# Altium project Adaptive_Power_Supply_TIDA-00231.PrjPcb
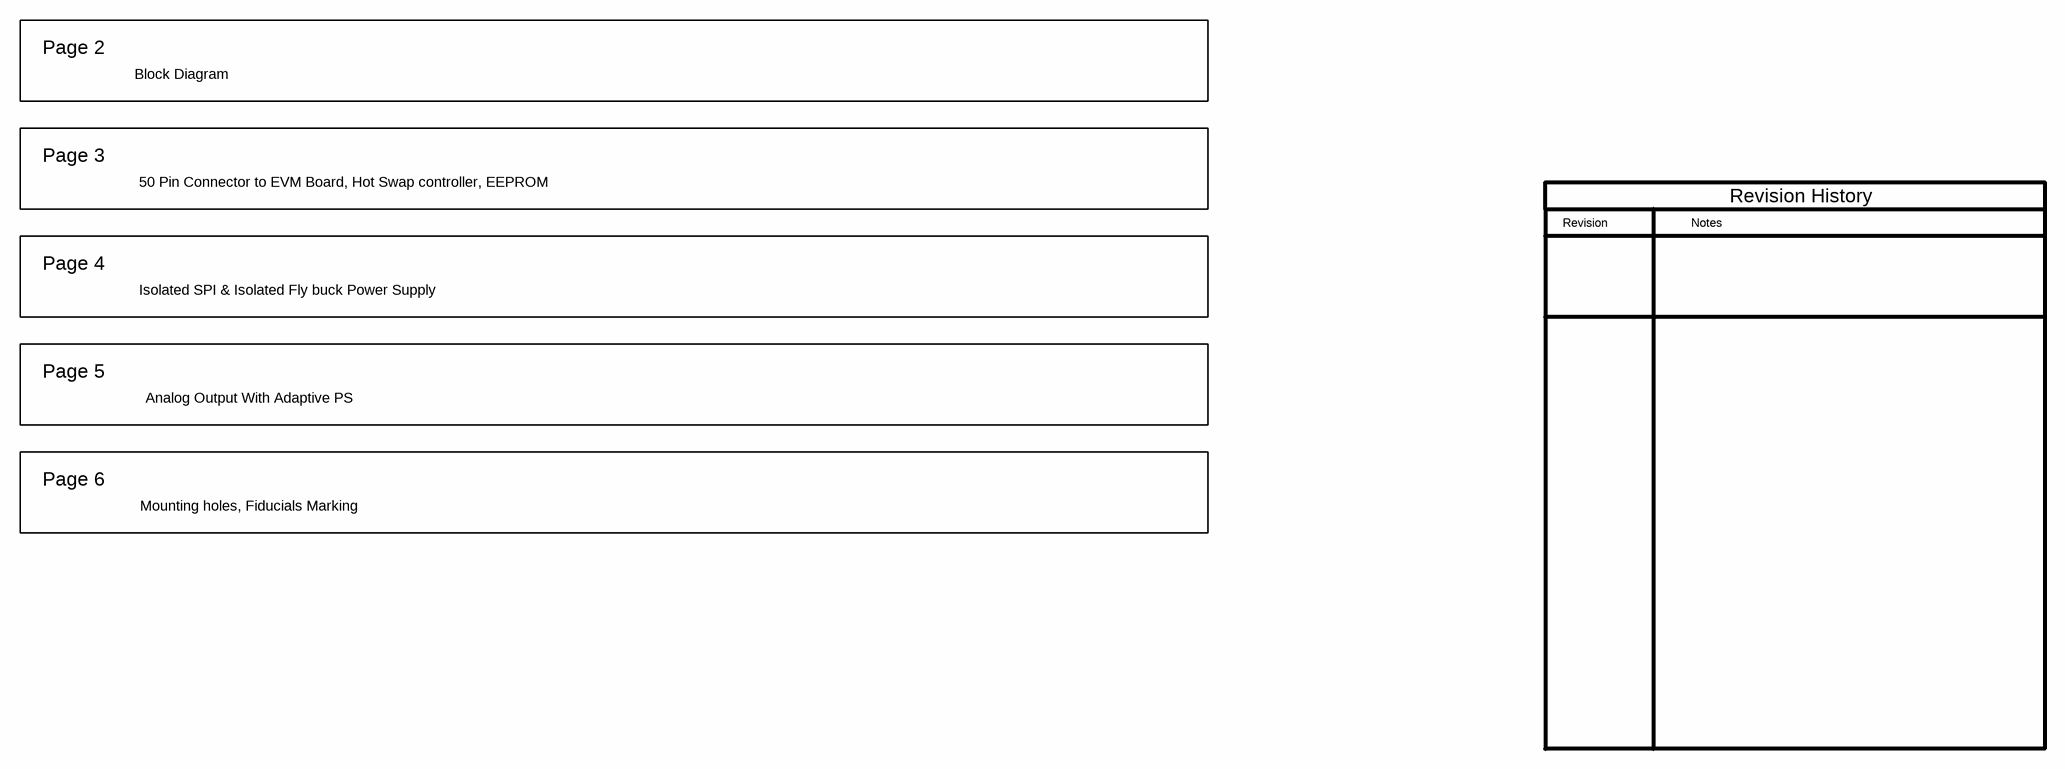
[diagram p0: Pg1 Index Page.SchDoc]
CopyrightYear: 2014; PCB_Layout: Sharanu; PCB_Rev: E1; PRJ_Customer: Public Release; PRJ_Engineer: Amol Gadkari; PRJ_Number: TIDA-00231; PRJ_Title: Adaptive Power Supply for DAC; SCH_Rev: E1; TechSupport: http://www.ti.com/support
6 sheets, 182 parts. Net scope: flat (ports and power ports of the same name join across sheets).
Board file: TIDA-00231.PcbDoc
Sheets:
  Pg1 Index Page.SchDoc
  Pg2 Block Diagram.SchDoc
  Pg3 Interboard conn, HS & EEPROM.SchDoc
  Pg4 ISO Power Supply, I2C & SPI Isolators.SchDoc
  Pg5 Analog Output & Adaptive PS.SchDoc
  Pg6 Hardware.SchDoc

## Sheet Pg1 Index Page.SchDoc
size 431 x 279 mm; Date: Not shown in title block; ApprovedBy: Not shown in title block; CheckedBy: Not shown in title block; Author: Not shown in title block; CompanyName: Not shown in title block; Engineer: Not shown in title block; Organization: Not shown in title block; Address1: Not shown in title block; Address2: Not shown in title block; Address3: Not shown in title block; Address4: Not shown in title block; DocumentNumber: 1; Revision: Use project parameter SCH_Rev; SheetNumber: 1; SheetTotal: 8; PageSetup: Record=PageOptions|CenterHorizontal=True|CenterVertical=True|PrintScale=0.62|XCorrection=1.00|YCorrection=1.00|PrintKind=0|BorderSize=5000000|LeftOffset=0|BottomOffset=0|Orientation=2|PaperLength=1000|PaperWidth=1000|Scale=100|PaperSource=15|PrintQuality=600|MediaType=1|DitherType=10|PaperKind=Letter|PrintScaleMode=1

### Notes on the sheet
- Page 2
- Block Diagram
- Page 3
- 50 Pin Connector to EVM Board, Hot Swap controller, EEPROM
- Revision History
- Page 4
- Revision
- Notes
- Isolated SPI & Isolated Fly buck Power Supply
- Page 5
- Analog Output With Adaptive PS
- Page 6
- Mounting holes, Fiducials Marking

## Sheet Pg2 Block Diagram.SchDoc
size 431 x 279 mm; Date: Not shown in title block; ApprovedBy: Not shown in title block; CheckedBy: Not shown in title block; Author: Not shown in title block; CompanyName: Not shown in title block; Engineer: Not shown in title block; Organization: Not shown in title block; Address1: Not shown in title block; Address2: Not shown in title block; Address3: Not shown in title block; Address4: Not shown in title block; DocumentNumber: 2; Revision: Use project parameter SCH_Rev; SheetNumber: 2; SheetTotal: 8; PageSetup: Record=PageOptions|CenterHorizontal=True|CenterVertical=True|PrintScale=1.00|XCorrection=1.00|YCorrection=1.00|PrintKind=0|BorderSize=5000000|LeftOffset=0|BottomOffset=0|Orientation=2|PaperLength=1000|PaperWidth=1000|Scale=100|PaperSource=15|PrintQuality=600|MediaType=1|DitherType=10|PaperKind=Letter|PrintScaleMode=1

## Sheet Pg3 Interboard conn, HS & EEPROM.SchDoc
size 431 x 279 mm; Date: Not shown in title block; ApprovedBy: Not shown in title block; CheckedBy: Not shown in title block; Author: Not shown in title block; CompanyName: Not shown in title block; Engineer: Not shown in title block; Organization: Not shown in title block; Address1: Not shown in title block; Address2: Not shown in title block; Address3: Not shown in title block; Address4: Not shown in title block; DocumentNumber: 3; Revision: Use project parameter SCH_Rev; SheetNumber: 3; SheetTotal: 8; PageSetup: Record=PageOptions|CenterHorizontal=True|CenterVertical=True|PrintScale=1.00|XCorrection=1.00|YCorrection=1.00|PrintKind=0|BorderSize=5000000|LeftOffset=0|BottomOffset=0|Orientation=2|PaperLength=1000|PaperWidth=1000|Scale=100|PaperSource=15|PrintQuality=600|MediaType=1|DitherType=10|PaperKind=Letter|PrintScaleMode=1
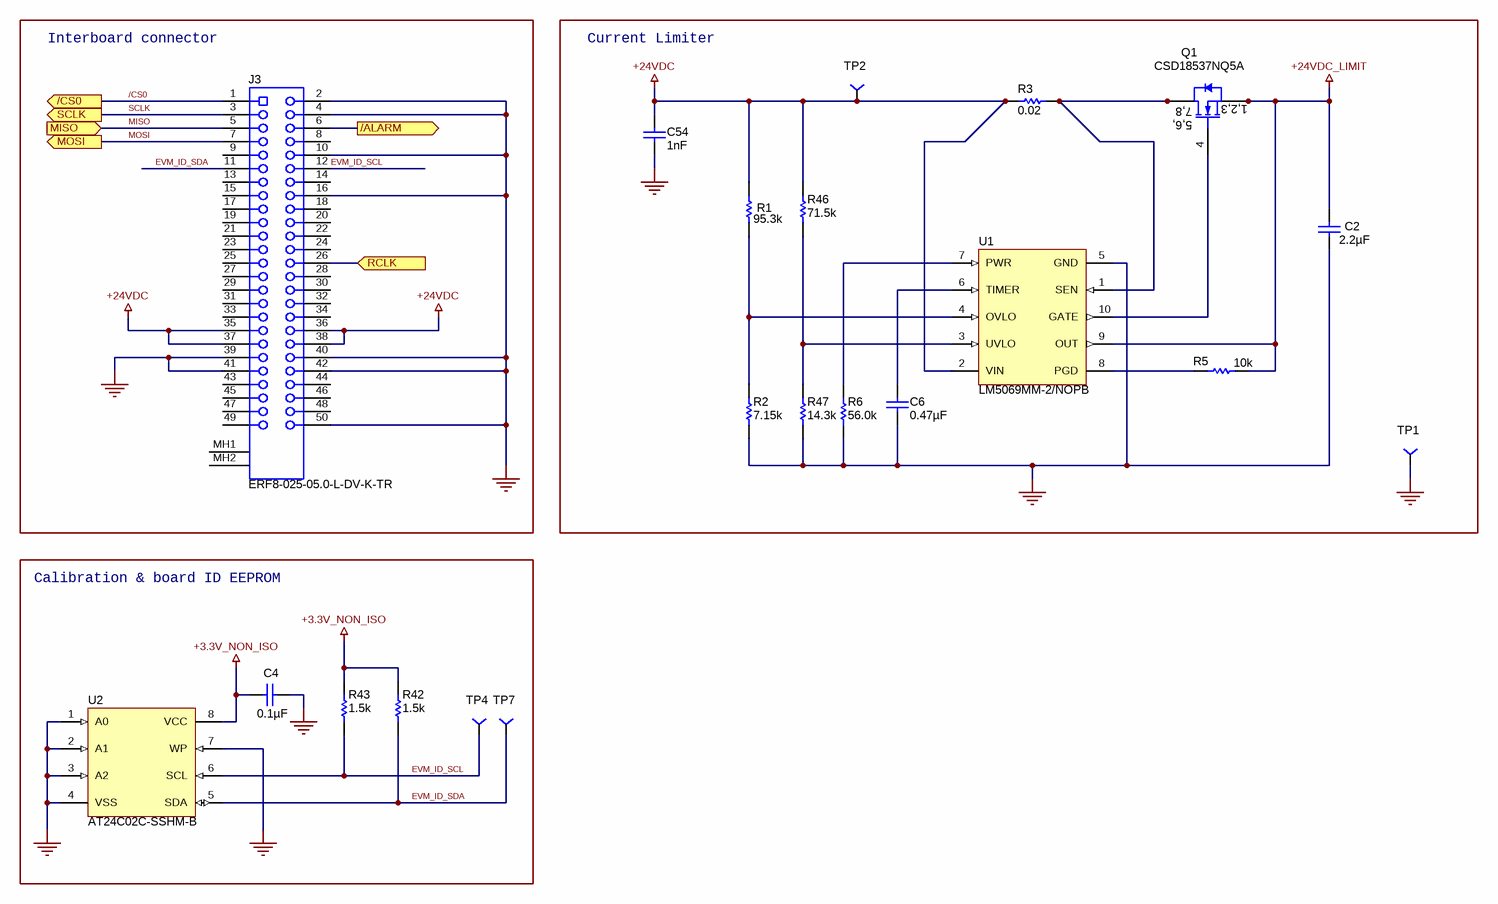
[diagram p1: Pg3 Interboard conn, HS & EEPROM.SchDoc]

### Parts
C2  ValueDisplayed: 2.2µF  [1210]  (hidden comment: GRM32ER72A225KA35L)
C4  ValueDisplayed: 0.1µF  [0603]  (hidden comment: C0603C104K5RACTU)
C6  ValueDisplayed: 0.47µF  [0603]  (hidden comment: UMK107ABJ474KA-T)
C54  ValueDisplayed: 1nF  [0603]  (hidden comment: 06031C102MAT2A)
J3  ERF8-025-05.0-L-DV-K-TR  [CONN_ERF8-025-05_0-L-DV-L-TR]
Q1  CSD18537NQ5A  [TRANS_NexFET_Q5A]
R1  value 95.3k  [0603]  (hidden comment: CRCW060395K3FKEA)
R2  value 7.15k  [0603]  (hidden comment: CRCW06037K15FKEA)
R3  value 0.02  [1206]  (hidden comment: PRL1632-R020-F-T1)
R5  value 10k  [0603]  (hidden comment: CRCW060310K0JNEA)
R6  value 56.0k  [0603]  (hidden comment: RG1608P-563-B-T5)
R42  value 1.5k  [0402]  (hidden comment: CRCW04021K50JNED)
R43  value 1.5k  [0402]  (hidden comment: CRCW04021K50JNED)
R46  value 71.5k  [0603]  (hidden comment: CRCW060371K5FKEA)
R47  value 14.3k  [0603]  (hidden comment: CRCW060314K3FKEA)
TP1  TP-040_RND  [TP1_PD40_D0.5_S50]  (value not drawn)
TP2  TP-040_RND  [TP1_PD40_D0.5_S50]  (value not drawn)
TP4  TP-040_RND  [TP1_PD40_D0.5_S50]  (value not drawn)
TP7  TP-040_RND  [TP1_PD40_D0.5_S50]  (value not drawn)
U1  LM5069MM-2/NOPB  [MUB10A_N]
U2  AT24C02C-SSHM-B  [SOIC-8]

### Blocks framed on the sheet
Interboard connector: J3
Current Limiter: C2 C6 C54 Q1 R1-R3 R5 R6 R46 R47 TP1 TP2 U1
Calibration & board ID EEPROM: C4 R42 R43 TP4 TP7 U2

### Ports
/ALARM (out), /CS0 (out), MISO (in), MOSI (out), RCLK (in), SCLK (out)

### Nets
+3.3V_NON_ISO: C4.2 R42.1 R43.1 U2.8(VCC)
+24VDC: C54.1 J3.35 J3.36 J3.37 J3.38 R1.2 R3.1 R46.2 TP2.1 U1.2(VIN)
+24VDC_LIMIT: C2.1 Q1.1(S) Q1.2(S) Q1.3(S) R5.2 U1.9(OUT)
GND: C2.2 C4.1 C6.2 C54.2 J3.2 J3.4 J3.10 J3.16 J3.39 J3.40 J3.41 J3.42 J3.50 R2.1 R6.1 R47.1 TP1.1 U1.5(GND) U2.1(A0) U2.2(A1) U2.3(A2) U2.4(VSS) U2.7(WP)
/ALARM: J3.6 ; port /ALARM
/CS0: J3.1 ; port /CS0
EVM_ID_SCL: J3.12 R43.2 TP4.1 U2.6(SCL)
EVM_ID_SDA: J3.11 R42.2 TP7.1 U2.5(SDA)
MISO: J3.5 ; port MISO
MOSI: J3.7 ; port MOSI
RCLK: J3.26 ; port RCLK
SCLK: J3.3 ; port SCLK
NetC6_1: C6.1 U1.6(TIMER)
NetQ1_4: Q1.4(G) U1.10(GATE)
NetQ1_5: Q1.5(D) Q1.6(D) Q1.7(D) Q1.8(D) Q1.9(D) R3.2 U1.1(SEN)
NetR1_1: R1.1 R2.2 U1.4(OVLO)
NetR5_1: R5.1 U1.8(PGD)
NetR6_2: R6.2 U1.7(PWR)
NetR46_1: R46.1 R47.2 U1.3(UVLO)

Not connected (* = marked no-connect by the designer): J3 8 9 13 14 15 17 18 19 20 21 22 23 24 25 27 28 29 30 31 32 33 34 43 44 45 46 47 48 49 MH1(51) MH2(52)

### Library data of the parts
C2 = GRM32ER72A225KA35L: CAP, CERM, 2.2uF, 100V, +/-10%, X7R, 1210; Manufacturer: MuRata; Polarized: N; CompType: Capacitor; U/M: EA; Cap_F: 0.0000022; Tolerance_%: 10; ESR_Ohm: 0.007; Value1: 0.007 ohm; VDC_V: 100; IRMS_A: 4.4; TaMin_C: -55; TaMax_C: 125
C4 = C0603C104K5RACTU: CAP, CERM, 0.1uF, 50V, +/-10%, X7R, 0603; Manufacturer: Kemet; Polarized: N; CompType: Capacitor; U/M: EA; Cap_F: 0.0000001; Tolerance_%: 10; Value1: Unknown; VDC_V: 50; TaMin_C: -55; TaMax_C: 125
C6 = UMK107ABJ474KA-T: CAP, CERM, 0.47uF, 50V, 10%, X5R, 0603; Manufacturer: Taiyo Yuden; Polarized: N; CompType: Capacitor; Cap_F: 0.00000047; Tolerance_%: 10; VDC_V: 50
C54 = 06031C102MAT2A: CAP, CERM, 1000pF, 100V, +/-20%, X7R, 0603; Manufacturer: AVX; Polarized: N; CompType: Capacitor; U/M: EA; Cap_F: 0.000000001; Tolerance_%: 20; ESR_Ohm: 0.276; Value1: 0.276 ohm; VDC_V: 100; TaMin_C: -55; TaMax_C: 125
J3 = ERF8-025-05.0-L-DV-K-TR: Receptacle, 0.8mm, 25x2, SMT; Manufacturer: Samtec; SymbolCreator: a0412235; CompType: Connector; U/M: EA
Q1 = CSD18537NQ5A: MOSFET, N-CH, 60V, 50A, SON 5x6mm; Manufacturer: Texas Instruments; Alternate Manufacturer: None; U/M: EA; ChType: N; VdsMax_V: 60; Value1: 0.036 ohm; Rdson45_Ohm: 0.036; Value2: 14 nC; QgTyp_nC: 14; Vgs_V: 20; IdsMax_A: 50
R1 = CRCW060395K3FKEA: RES, 95.3k ohm, 1%, 0.1W, 0603; Manufacturer: Vishay-Dale; CompType: Resistor; Res_ohm: 95300; Value_Code: 95k3; Tolerance_%: 1; Power_W: 0.1; VDC_V: 75; TempCo: 100 ppm/C; EIA_Code: E96; U/M: EA
R2 = CRCW06037K15FKEA: RES, 7.15k ohm, 1%, 0.1W, 0603; Manufacturer: Vishay-Dale; CompType: Resistor; Res_ohm: 7150; Value_Code: 7k15; Tolerance_%: 1; Power_W: 0.1; VDC_V: 75; TempCo: 100 ppm/C; EIA_Code: E96; U/M: EA
R3 = PRL1632-R020-F-T1: RES, 0.02 ohm, 1%, 1W, 1206; Manufacturer: Susumu Co Ltd; CompType: Resistor; Value_Code: R020; Tolerance_%: 1; TempCo: 100 ppm/C; EIA_Code: E96; U/M: EA
R5 = CRCW060310K0JNEA: RES, 10k ohm, 5%, 0.1W, 0603; Manufacturer: Vishay-Dale; CompType: Resistor; Res_ohm: 10000; Value_Code: 10k0; Tolerance_%: 5; Power_W: 0.1; VDC_V: 75; TempCo: 200 ppm/C; EIA_Code: E24; U/M: EA
R6 = RG1608P-563-B-T5: RES, 56.0k ohm, 0.1%, 0.1W, 0603; Manufacturer: Susumu Co Ltd; CompType: Resistor; Res_ohm: 56000; Value_Code: 56k0; Tolerance_%: 0.1; VDC_V: 75; TempCo: 25 ppm/C; U/M: EA
R42 R43 = CRCW04021K50JNED: RES, 1.5k ohm, 5%, 0.063W, 0402; Manufacturer: Vishay-Dale; CompType: Resistor; Res_ohm: 1500; Value_Code: 1k50; Tolerance_%: 5; Power_W: 0.063; VDC_V: 50; TempCo: 200 ppm/C; EIA_Code: E24; U/M: EA
R46 = CRCW060371K5FKEA: RES, 71.5k ohm, 1%, 0.1W, 0603; Manufacturer: Vishay-Dale; CompType: Resistor; Res_ohm: 71500; Value_Code: 71k5; Tolerance_%: 1; Power_W: 0.1; VDC_V: 75; TempCo: 100 ppm/C; EIA_Code: E96; U/M: EA
R47 = CRCW060314K3FKEA: RES, 14.3k ohm, 1%, 0.1W, 0603; Manufacturer: Vishay-Dale; CompType: Resistor; Res_ohm: 14300; Value_Code: 14k3; Tolerance_%: 1; Power_W: 0.1; VDC_V: 75; TempCo: 100 ppm/C; EIA_Code: E96; U/M: EA
TP1 TP2 TP4 TP7 = TP-040_RND: Test Point 40mil pad 20mil drill; Manufacturer: STD; Description: Test Point, O.040 Hole; Value: STD
U1 = LM5069MM-2/NOPB: Positive High Voltage Hot Swap / Inrush Current Controller with Power Limiting, 10-pin MSOP, Pb-Free; Manufacturer: National Semiconductor; PackageTopMarking: ZXTT*SNBB; PowerWise: N; CompType: MiscPower
U2 = AT24C02C-SSHM-B: IC, EEPROM, 2KBIT, 1MHZ, SOIC-8; Manufacturer: Atmel; SymbolCreator: a0411947

## Sheet Pg4 ISO Power Supply, I2C & SPI Isolators.SchDoc
size 431 x 279 mm; Date: Not shown in title block; ApprovedBy: Not shown in title block; CheckedBy: Not shown in title block; Author: Not shown in title block; CompanyName: Not shown in title block; Engineer: Not shown in title block; Organization: Not shown in title block; Address1: Not shown in title block; Address2: Not shown in title block; Address3: Not shown in title block; Address4: Not shown in title block; DocumentNumber: 4; Revision: Use project parameter SCH_Rev; SheetNumber: 4; SheetTotal: 8; PageSetup: Record=PageOptions|CenterHorizontal=True|CenterVertical=True|PrintScale=0.62|XCorrection=1.00|YCorrection=1.00|PrintKind=0|BorderSize=5000000|LeftOffset=0|BottomOffset=0|Orientation=2|PaperLength=1000|PaperWidth=1000|Scale=100|PaperSource=15|PrintQuality=600|MediaType=1|DitherType=10|PaperKind=Letter|PrintScaleMode=1
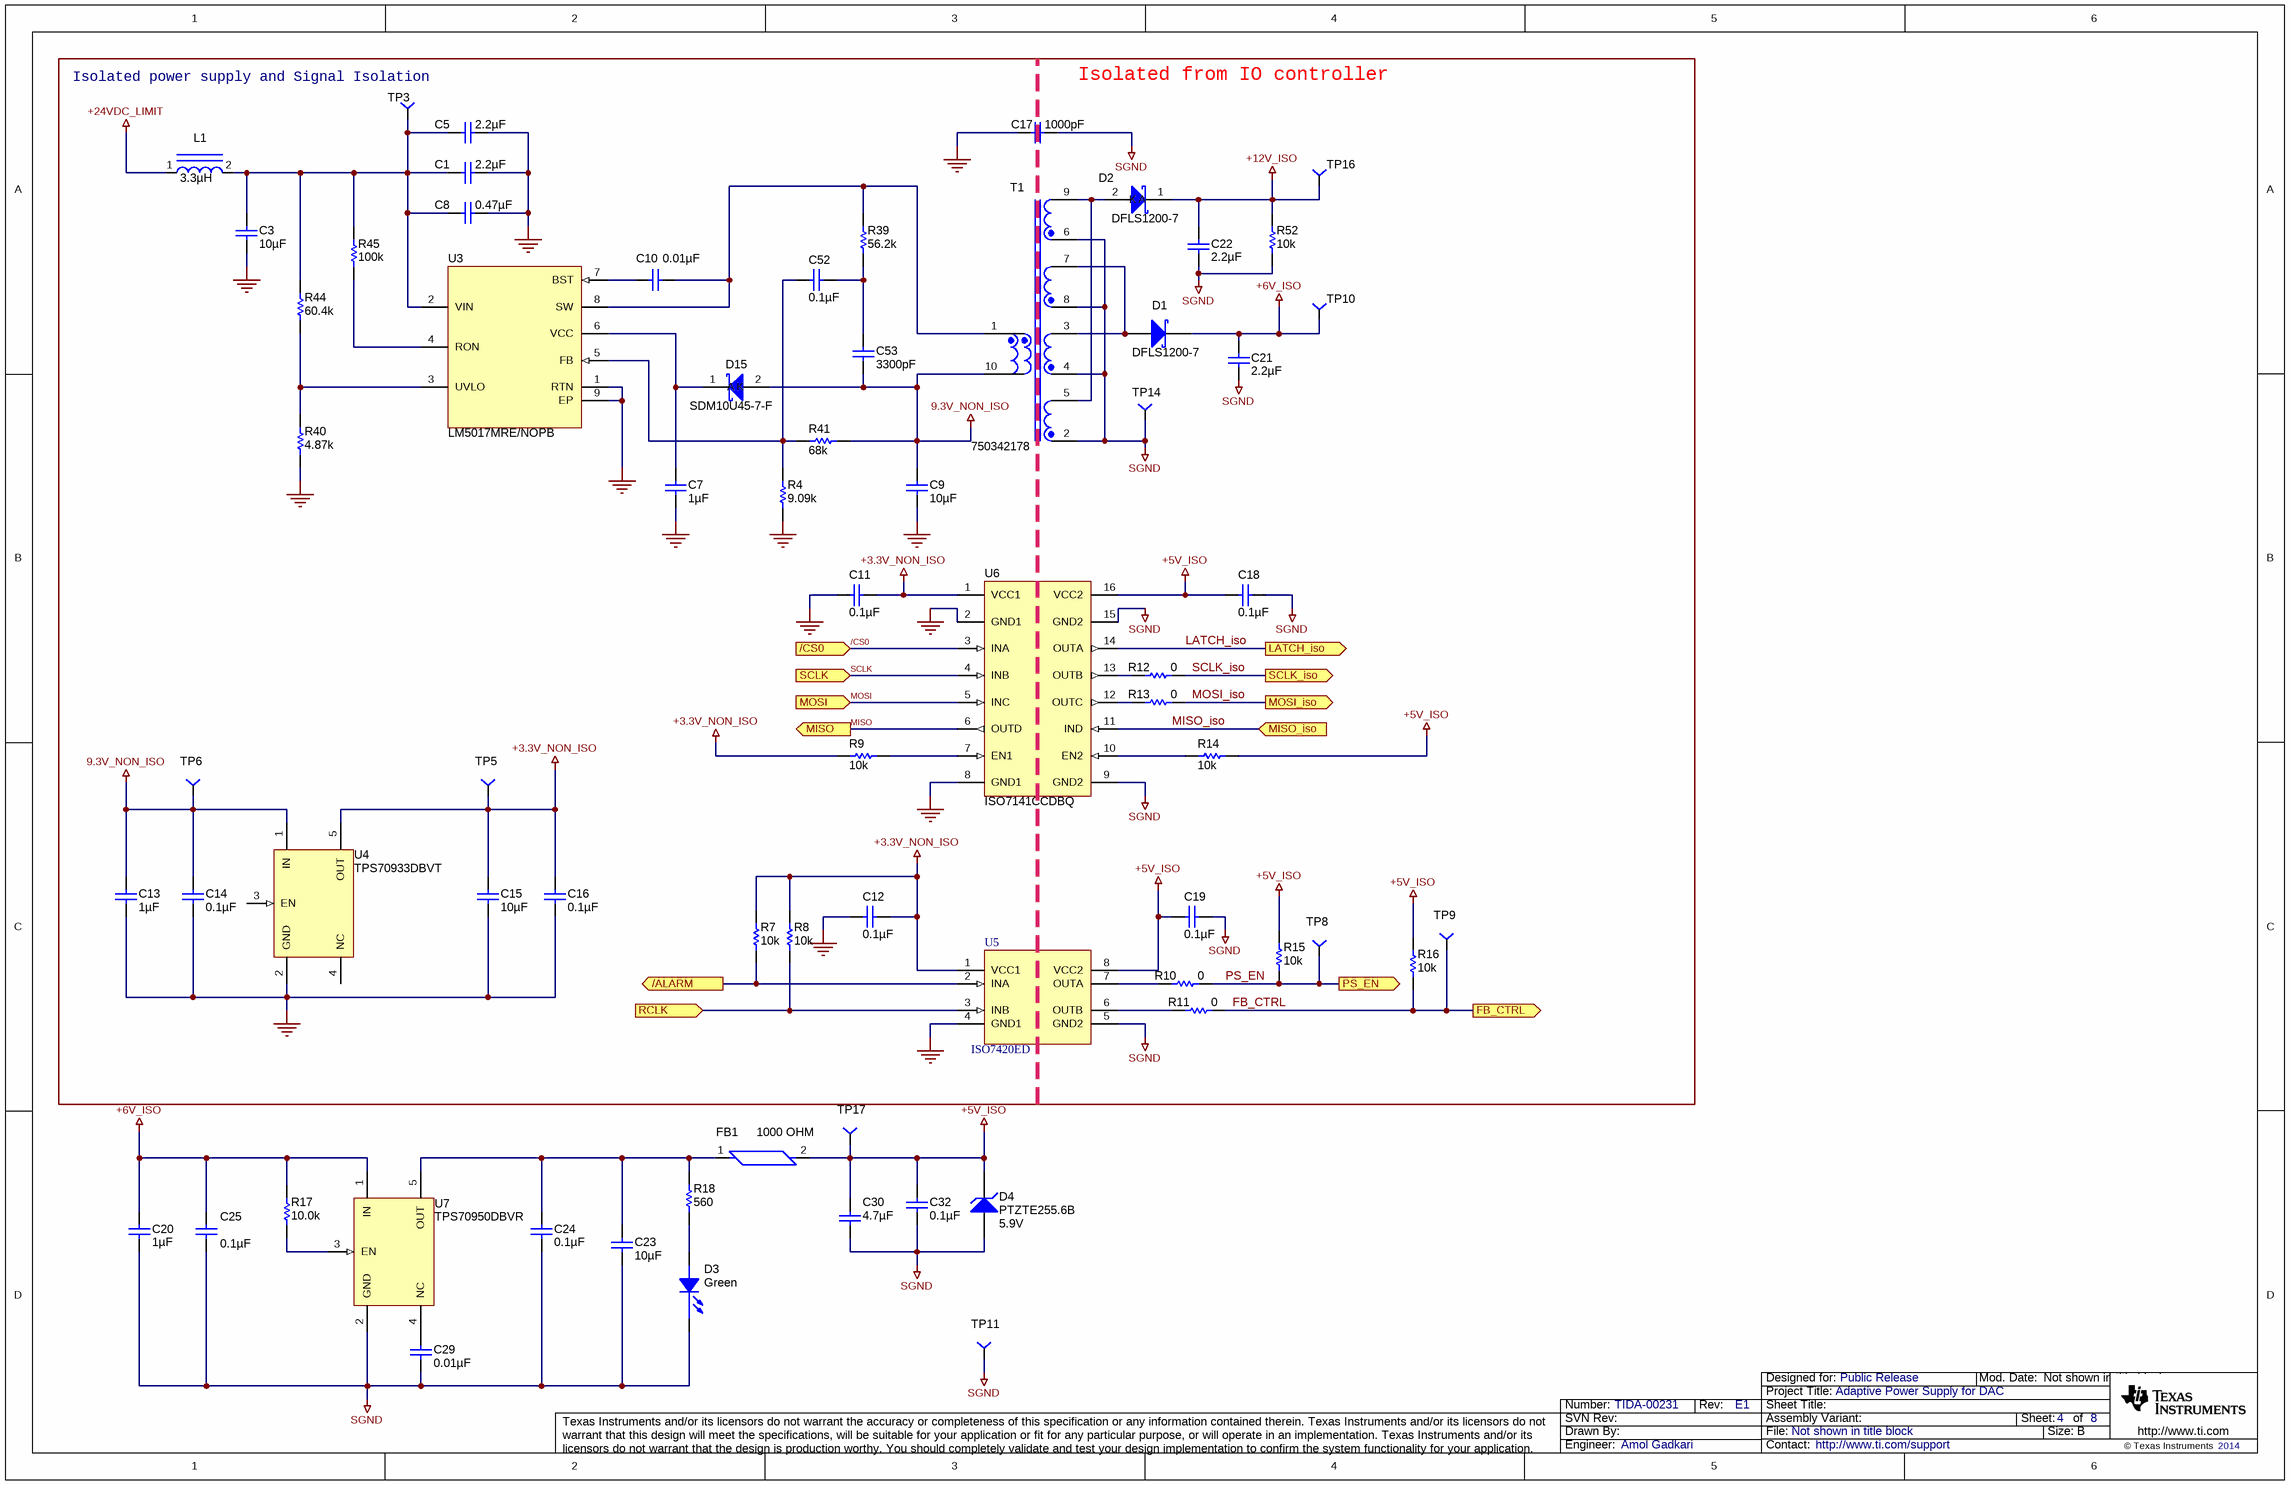
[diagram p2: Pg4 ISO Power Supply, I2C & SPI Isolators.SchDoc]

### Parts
C1  ValueDisplayed: 2.2µF  [1210]  (hidden comment: GRM32ER72A225KA35L)
C3  ValueDisplayed: 10µF  [1210]  (hidden comment: GRM32ER71H106KA12L)
C5  ValueDisplayed: 2.2µF  [1210]  (hidden comment: GRM32ER72A225KA35L)
C7  ValueDisplayed: 1µF  [0603]  (hidden comment: GRM188R61H105KAALD)
C8  ValueDisplayed: 0.47µF  [1206]  (hidden comment: GRM31MR72A474KA35L)
C9  ValueDisplayed: 10µF  [1210]  (hidden comment: GMK325AB7106MM-T)
C10  ValueDisplayed: 0.01µF  [0603]  (hidden comment: 06031C103JAT2A)
C11  ValueDisplayed: 0.1µF  [0603]  (hidden comment: C0603C104K5RACTU)
C12  ValueDisplayed: 0.1µF  [0603]  (hidden comment: C0603C104K5RACTU)
C13  ValueDisplayed: 1µF  [0805]  (hidden comment: 08055C105KAT2A)
C14  ValueDisplayed: 0.1µF  [0603]  (hidden comment: C0603C104K5RACTU)
C15  ValueDisplayed: 10µF  [0805]  (hidden comment: 0805YD106MAT2A)
C16  ValueDisplayed: 0.1µF  [0603]  (hidden comment: C0603C104K5RACTU)
C17  value 1000pF  [1206]  (hidden comment: 202R18W102KV4E)
C18  ValueDisplayed: 0.1µF  [0603]  (hidden comment: C0603C104K5RACTU)
C19  ValueDisplayed: 0.1µF  [0603]  (hidden comment: C0603C104K5RACTU)
C20  ValueDisplayed: 1µF  [0805]  (hidden comment: 08055C105KAT2A)
C21  ValueDisplayed: 2.2µF  [0805_HV]  (hidden comment: GRM21BR71E225KA73L)
C22  ValueDisplayed: 2.2µF  [0805_HV]  (hidden comment: GRM21BR71E225KA73L)
C23  ValueDisplayed: 10µF  [0805]  (hidden comment: 0805YD106MAT2A)
C24  ValueDisplayed: 0.1µF  [0603]  (hidden comment: C0603C104K5RACTU)
C25  ValueDisplayed: 0.1µF  [0603]  (hidden comment: C0603C104K5RACTU)
C29  ValueDisplayed: 0.01µF  [0603]  (hidden comment: C0603C103J5RACTU)
C30  ValueDisplayed: 4.7µF  [0805_HV]  (hidden comment: C2012X5R1H475K125AB)
C32  ValueDisplayed: 0.1µF  [0603]  (hidden comment: C0603C104K5RACTU)
C52  ValueDisplayed: 0.1µF  [0603]  (hidden comment: GRM188R72A104KA35D)
C53  ValueDisplayed: 3300pF  [0603]  (hidden comment: 06031C332JAT2A)
D1  DFLS1200-7  [powerDI123]
D2  DFLS1200-7  [powerDI123]
D3  value Green  [LED0603AA]  (hidden comment: LED_LG L29K-G2J1-24-Z)
D4  PTZTE255.6B  value 5.9V  [SMA]
D15  SDM10U45-7-F  [SOD-523]
FB1  1000 OHM  [FB0603]
L1  3.3µH  [IND_B82422H]
R4  value 9.09k  [0603]  (hidden comment: CRCW06039K09FKEA)
R7  value 10k  [0402]  (hidden comment: CRCW040210K0JNED)
R8  value 10k  [0402]  (hidden comment: CRCW040210K0JNED)
R9  value 10k  [0402]  (hidden comment: CRCW040210K0JNED)
R10  value 0  [0402]  (hidden comment: RC0402JR-070RL)
R11  value 0  [0402]  (hidden comment: RC0402JR-070RL)
R12  value 0  [0402]  (hidden comment: RC0402JR-070RL)
R13  value 0  [0402]  (hidden comment: RC0402JR-070RL)
R14  value 10k  [0402]  (hidden comment: CRCW040210K0JNED)
R15  value 10k  [0402]  (hidden comment: CRCW040210K0JNED)
R16  value 10k  [0402]  (hidden comment: CRCW040210K0JNED)
R17  value 10.0k  [0603]  (hidden comment: CRCW060310K0FKEA)
R18  value 560  [0603]  (hidden comment: CRCW0603560RJNEA)
R39  value 56.2k  [0603]  (hidden comment: RT0603BRD0756K2L)
R40  value 4.87k  [0603]  (hidden comment: RC0603FR-074K87L)
R41  value 68k  [0603]  (hidden comment: CRCW060368K0JNEA)
R44  value 60.4k  [0603]  (hidden comment: RT0603BRD0760K4L)
R45  value 100k  [0603]  (hidden comment: CRCW0603100KFKEA)
R52  value 10k  [0603]  (hidden comment: CRCW060310K0JNEA)
T1  750342178  [WURTH_750313995]
TP3  TP1_PD40_D0.5_S50  [TP1_PD40_D0.5_S50]  (value not drawn)
TP5  TP1_PD40_D0.5_S50  [TP1_PD40_D0.5_S50]  (value not drawn)
TP6  TP1_PD40_D0.5_S50  [TP1_PD40_D0.5_S50]  (value not drawn)
TP8  TP1_PD40_D0.5_S50  [TP1_PD40_D0.5_S50]  (value not drawn)
TP9  TP1_PD40_D0.5_S50  [TP1_PD40_D0.5_S50]  (value not drawn)
TP10  TP1_PD40_D0.5_S50  [TP1_PD40_D0.5_S50]  (value not drawn)
TP11  TP1_PD40_D0.5_S50  [TP1_PD40_D0.5_S50]  (value not drawn)
TP14  TP1_PD40_D0.5_S50  [TP1_PD40_D0.5_S50]  (value not drawn)
TP16  TP1_PD40_D0.5_S50  [TP1_PD40_D0.5_S50]  (value not drawn)
TP17  TP1_PD40_D0.5_S50  [TP1_PD40_D0.5_S50]  (value not drawn)
U3  LM5017MRE/NOPB  [DDA0008B_N]
U4  TPS70933DBVT  [DBV0005A_N]
U5  ISO7420ED  [D0008A_N]
U6  ISO7141CCDBQ  [DBQ0016A_N]
U7  TPS70950DBVR  [DBV0005A_N]

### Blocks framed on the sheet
Isolated from IO controller: C1 C3 C5 C7-C19 C21 C22 C52 C53 D1 D2 D15 L1 R4 R7-R16 R39-R41 R44 R45 R52 T1 TP3 TP5 TP6 TP8-TP10 TP14 TP16 U3-U6

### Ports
/ALARM (out), /CS0 (in), FB_CTRL (out), LATCH_iso (out), MISO (out), MISO_iso (in), MOSI (in), MOSI_iso (out), PS_EN (out), RCLK (in), SCLK (in), SCLK_iso (out)

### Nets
9.3V_NON_ISO: C9.1 C13.1 C14.1 C53.2 D15.2(A) R41.2 T1.10 TP6.1 U4.1(IN)
+3.3V_NON_ISO: C11.2 C12.2 C15.1 C16.1 R7.1 R8.2 R9.1 TP5.1 U4.5(OUT) U5.1(VCC1) U6.1(VCC1)
+5V_ISO: C18.1 C19.1 C30.1 C32.1 D4.1(K) FB1.2 R14.2 R15.2 R16.2 TP17.1 U5.8(VCC2) U6.16(VCC2)
+6V_ISO: C20.1 C21.2 C25.1 D1.1(K) R17.2 TP10.1 U7.1(IN)
+12V_ISO: C22.1 D2.1(K) R52.2 TP16.1
+24VDC_LIMIT: L1.1
GND: C1.1 C3.2 C5.1 C7.2 C8.1 C9.2 C11.1 C12.1 C13.2 C14.2 C15.2 C16.2 C17.1 R4.1 R40.1 U3.1(RTN) U3.9(EP) U4.2(GND) U5.4(GND1) U6.2(GND1) U6.8(GND1)
SGND: C17.2 C18.2 C19.2 C20.2 C21.1 C22.2 C23.2 C24.2 C25.2 C29.2 C30.2 C32.2 D3.1(C) D4.2(A) R52.1 T1.2 T1.4 T1.6 T1.8 TP11.1 TP14.1 U5.5(GND2) U6.9(GND2) U6.15(GND2) U7.2(GND)
/ALARM: R7.2 U5.2(INA) ; port /ALARM
/CS0: U6.3(INA) ; port /CS0
FB_CTRL: R11.2 R16.1 TP9.1 ; port FB_CTRL
LATCH_iso: U6.14(OUTA) ; port LATCH_iso
MISO: U6.6(OUTD) ; port MISO
MISO_iso: U6.11(IND) ; port MISO_iso
MOSI: U6.5(INC) ; port MOSI
MOSI_iso: R13.2 ; port MOSI_iso
PS_EN: R10.2 R15.1 TP8.1 ; port PS_EN
RCLK: R8.1 U5.3(INB) ; port RCLK
SCLK: U6.4(INB) ; port SCLK
SCLK_iso: R12.2 ; port SCLK_iso
NetC1_2: C1.2 C3.1 C5.2 C8.2 L1.2 R44.2 R45.2 TP3.1 U3.2(VIN)
NetC7_1: C7.1 D15.1(K) U3.6(VCC)
NetC10_1: C10.1 U3.7(BST)
NetC10_2: C10.2 R39.2 T1.1 U3.8(SW)
NetC23_1: C23.1 C24.1 FB1.1 R18.2 U7.5(OUT)
NetC29_1: C29.1 U7.4(NC)
NetC52_1: C52.1 C53.1 R39.1
NetC52_2: C52.2 R4.2 R41.1 U3.5(FB)
NetD1_2: D1.2(A) T1.3 T1.7
NetD2_2: D2.2(A) T1.5 T1.9
NetD3_2: D3.2(A) R18.1
NetR9_2: R9.2 U6.7(EN1)
NetR10_1: R10.1 U5.7(OUTA)
NetR11_1: R11.1 U5.6(OUTB)
NetR12_1: R12.1 U6.13(OUTB)
NetR13_1: R13.1 U6.12(OUTC)
NetR14_1: R14.1 U6.10(EN2)
NetR17_1: R17.1 U7.3(EN)
NetR40_2: R40.2 R44.1 U3.3(UVLO)
NetR45_1: R45.1 U3.4(RON)

Not connected (* = marked no-connect by the designer): U4 3(EN) 4(NC)

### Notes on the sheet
- (near TP3) Isolated power supply and Signal Isolation

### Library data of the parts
C1 C5 = GRM32ER72A225KA35L: as C2 on sheet Pg3 Interboard conn, HS & EEPROM
C3 = GRM32ER71H106KA12L: CAP, CERM, 10uF, 50V, +/-10%, X7R, 1210; Manufacturer: MuRata; Polarized: N; CompType: Capacitor; U/M: EA; Cap_F: 0.00001; Tolerance_%: 10; Value1: Unknown; VDC_V: 50; TaMin_C: -55; TaMax_C: 125
C7 = GRM188R61H105KAALD: CAP, CERM, 1uF, 50V, +/-10%, X5R, 0603; Manufacturer: MuRata; Polarized: N; CompType: Capacitor; U/M: EA; Cap_F: 0.000001; Tolerance_%: 10; Value1: Unknown; VDC_V: 50; TaMin_C: -55; TaMax_C: 85
C8 = GRM31MR72A474KA35L: CAP, CERM, 0.47uF, 100V, +/-10%, X7R, 1206; Manufacturer: MuRata; Polarized: N; CompType: Capacitor; U/M: EA; Cap_F: 0.00000047; Tolerance_%: 10; Value1: Unknown; VDC_V: 100; TaMin_C: -55; TaMax_C: 125
C9 = GMK325AB7106MM-T: CAP, CERM, 10uF, 35V, +/-20%, X7R, 1210; Manufacturer: Taiyo Yuden; Polarized: N; CompType: Capacitor; U/M: EA; Cap_F: 0.00001; Tolerance_%: 20; Value1: Unknown; VDC_V: 35; TaMin_C: -55; TaMax_C: 125
C10 = 06031C103JAT2A: CAP, CERM, 0.01uF, 100V, +/-5%, X7R, 0603; Manufacturer: AVX; Polarized: N; CompType: Capacitor; U/M: EA; Cap_F: 0.00000001; Tolerance_%: 5; ESR_Ohm: 0.098; Value1: 0.098 ohm; VDC_V: 100; TaMin_C: -55; TaMax_C: 125
C11 C12 C14 C16 C18 C19 C24 C25 C32 = C0603C104K5RACTU: as C4 on sheet Pg3 Interboard conn, HS & EEPROM
C13 C20 = 08055C105KAT2A: CAP, CERM, 1uF, 50V, +/-10%, X7R, 0805; Manufacturer: AVX; Polarized: N; CompType: Capacitor; U/M: EA; Cap_F: 0.000001; Tolerance_%: 10; Value1: Unknown; VDC_V: 50; TaMin_C: -55; TaMax_C: 125
C15 C23 = 0805YD106MAT2A: CAP, CERM, 10uF, 16V, +/-20%, X5R, 0805; Manufacturer: AVX; Polarized: N; CompType: Capacitor; U/M: EA; Cap_F: 0.00001; Tolerance_%: 20; Value1: Unknown; VDC_V: 16; TaMin_C: -55; TaMax_C: 85
C17 = 202R18W102KV4E: CAP, CERM, 1000pF, 2KV 10% X7R 1206; Manufacturer: Johanson Dielectrics Inc; Polarized: N; CompType: Capacitor; Cap_F: 0.000000001; Tolerance_%: 0
C21 C22 = GRM21BR71E225KA73L: CAP, CERM, 2.2uF, 25V, +/-10%, X7R, 0805; Manufacturer: MuRata; Polarized: N; CompType: Capacitor; U/M: EA; Cap_F: 0.0000022; Tolerance_%: 10; ESR_Ohm: 0.005; Value1: 0.005 ohm; VDC_V: 25; TaMin_C: -55; TaMax_C: 125; Cap_Case: 0805
C29 = C0603C103J5RACTU: CAP, CERM, 0.01uF, 50V, +/-5%, X7R, 0603; Manufacturer: Kemet; Polarized: N; CompType: Capacitor; U/M: EA; Cap_F: 0.00000001; Tolerance_%: 5; Value1: Unknown; VDC_V: 50; TaMin_C: -55; TaMax_C: 125
C30 = C2012X5R1H475K125AB: CAP, CERM, 4.7uF, 50V, +/-10%, X5R, 0805; Manufacturer: TDK; Polarized: N; CompType: Capacitor; U/M: EA; Cap_F: 0.0000047; Tolerance_%: 10; Value1: Unknown; VDC_V: 50; TaMin_C: -55; TaMax_C: 85; Cap_Case: 0805
C52 = GRM188R72A104KA35D: CAP, CERM, 0.1uF, 100V, +/-10%, X7R, 0603; Manufacturer: MuRata; Polarized: N; CompType: Capacitor; U/M: EA; Cap_F: 0.0000001; Tolerance_%: 10; Value1: Unknown; VDC_V: 100; TaMin_C: -55; TaMax_C: 125
C53 = 06031C332JAT2A: CAP, CERM, 3300pF, 100V, +/-5%, X7R, 0603; Manufacturer: AVX; Polarized: N; CompType: Capacitor; U/M: EA; Cap_F: 0.0000000033; Tolerance_%: 5; ESR_Ohm: 0.159; Value1: 0.159 ohm; VDC_V: 100; TaMin_C: -55; TaMax_C: 125
D1 D2 = DFLS1200-7: Diode, Schottky, 200V, 1A, PowerDI123; Manufacturer: Diodes Inc.; U/M: EA; Vf_V: 0.85; Value2: 0.85V; Io_A: 1; Vr_V: 200; TJmax_C: 175; RJC_CperW: 7
D3 = LED_LG L29K-G2J1-24-Z: LED SmartLED Green 570NM; Manufacturer: OSRAM; SymbolCreator: x0120606
D4 = PTZTE255.6B: DIODE ZENER 5.9V 1W PMDS; Manufacturer: Rohm Semiconductor; U/M: EA; Vz_V: 5.9
D15 = SDM10U45-7-F: Diode, Schottky, 45V, 0.1A, SOD-523; Manufacturer: Diodes Inc.; U/M: EA; Vf_V: 0.58; Value2: 0.58V; Io_A: 0.1; Vr_V: 45; TJmax_C: 125
FB1 = MMZ1608B102C: FERRITE CHIP 1000 OHM 300MA 0603; Manufacturer: TDK Corporation; CompType: Ferrite Bead
L1 = IND_ELJEA_SERIES: Inductor, Chip, ±10%; Manufacturer: EPCOS INC.; PartNumber: B82422H1332K; Area: 28000; Description: INDUCTOR 3.3UH 770MA 1210 10%
R4 = CRCW06039K09FKEA: RES, 9.09k ohm, 1%, 0.1W, 0603; Manufacturer: Vishay-Dale; CompType: Resistor; Res_ohm: 9090; Value_Code: 9k09; Tolerance_%: 1; Power_W: 0.1; VDC_V: 75; TempCo: 100 ppm/C; EIA_Code: E96; U/M: EA
R7-R9 R14-R16 = CRCW040210K0JNED: RES, 10k ohm, 5%, 0.063W, 0402; Manufacturer: Vishay-Dale; CompType: Resistor; Res_ohm: 10000; Value_Code: 10k0; Tolerance_%: 5; Power_W: 0.063; VDC_V: 50; TempCo: 200 ppm/C; EIA_Code: E24; U/M: EA
R10-R13 = RC0402JR-070RL: RES, 0 ohm, 5%, 0.063W, 0402; Manufacturer: Yageo America; CompType: Resistor; Value_Code: 0000; Tolerance_%: 5; Power_W: 0.063; VDC_V: 50; TempCo: 200 ppm/C; EIA_Code: E24; U/M: EA
R17 = CRCW060310K0FKEA: RES, 10.0k ohm, 1%, 0.1W, 0603; Manufacturer: Vishay-Dale; CompType: Resistor; Res_ohm: 10000; Value_Code: 10k0; Tolerance_%: 1; Power_W: 0.1; VDC_V: 75; TempCo: 100 ppm/C; EIA_Code: E96; U/M: EA
R18 = CRCW0603560RJNEA: RES, 560 ohm, 5%, 0.1W, 0603; Manufacturer: Vishay-Dale; CompType: Resistor; Value_Code: 560R; Tolerance_%: 5; Power_W: 0.1; VDC_V: 75; TempCo: 200 ppm/C; EIA_Code: E24; U/M: EA
R39 = RT0603BRD0756K2L: RES, 56.2k ohm, 0.1%, 0.1W, 0603; Manufacturer: Yageo America; CompType: Resistor; Res_ohm: 56200; Value_Code: 56k2; Tolerance_%: 0.1; VDC_V: 75; TempCo: 25 ppm/C; EIA_Code: E192; U/M: EA
R40 = RC0603FR-074K87L: RES, 4.87k ohm, 1%, 0.1W, 0603; Manufacturer: Yageo America; CompType: Resistor; Res_ohm: 4870; Value_Code: 4k87; Tolerance_%: 1; Power_W: 0.1; VDC_V: 150; TempCo: 200 ppm/C; EIA_Code: E96; U/M: EA
R41 = CRCW060368K0JNEA: RES, 68k ohm, 5%, 0.1W, 0603; Manufacturer: Vishay-Dale; CompType: Resistor; Res_ohm: 68000; Value_Code: 68k0; Tolerance_%: 5; Power_W: 0.1; VDC_V: 75; TempCo: 200 ppm/C; EIA_Code: E24; U/M: EA
R44 = RT0603BRD0760K4L: RES, 60.4k ohm, 0.1%, 0.1W, 0603; Manufacturer: Yageo America; CompType: Resistor; Res_ohm: 60400; Value_Code: 60k4; Tolerance_%: 0.1; VDC_V: 75; TempCo: 25 ppm/C; EIA_Code: E192; U/M: EA
R45 = CRCW0603100KFKEA: RES, 100k ohm, 1%, 0.1W, 0603; Manufacturer: Vishay-Dale; CompType: Resistor; Res_ohm: 100000; Tolerance_%: 1; Power_W: 0.1; VDC_V: 75; TempCo: 100 ppm/C; EIA_Code: E96; U/M: EA
R52 = CRCW060310K0JNEA: as R5 on sheet Pg3 Interboard conn, HS & EEPROM
T1 = 750313995: Transformer, 50uH, SMT; Manufacturer: Wurth Elektronik eiSos; SymbolCreator: a0411947; DCR_Ohm: 0.11; LeakageL: 0.130uH; U/M: EA
TP3 TP5 TP6 TP8-TP11 TP14 TP16 TP17 = TP-040_RND: as TP1 on sheet Pg3 Interboard conn, HS & EEPROM
U3 = LM5017MRE/NOPB: 100V, 600mA Constant On-Time Synchronous Buck Regulator, DDA0008B; Alternate Manufacturer: None; Manufacturer: Texas Instruments; SymbolCreator: a0412235; CompType: IC; U/M: EA
U4 = TPS70933DBVT: IC REG LDO 3.3V 0.15A SOT23-5; Alternate Manufacturer: None; Manufacturer: Texas Instruments; SymbolCreator: a0411947; U/M: EA
U5 = ISO7420ED: 50 Mbps Low-Power Dual Channels Digital Isolator, 3.3 V / 5 V, -40 to +125 degC, 8-pin SOIC (D), Green (RoHS & no Sb/Br); Manufacturer: Texas Instruments; Alternate PartNumber: Equivalent; Datarate(Mbps): 50; Input Noise Filter: None; Insulation Rating(VRMS): 2500; Prop Delay(Max)(ns): 11; Rating: Catalog; Supply Voltage(s)(V): 3.3, 5; TTL/CMOS Input Threshold: TTL
U6 = ISO7141CCDBQ: 4242-VPK Small-Footprint and Low-Power Quad Channels Digital Isolators, DBQ0016A; Alternate Manufacturer: None; Manufacturer: Texas Instruments; SymbolCreator: a0799628; CompType: IC; U/M: EA
U7 = TPS70950DBVR: IC REG LDO 5V 0.15A SOT23-5; Alternate Manufacturer: None; Manufacturer: Texas Instruments; SymbolCreator: a0411947; U/M: EA

## Sheet Pg5 Analog Output & Adaptive PS.SchDoc
size 431 x 279 mm; Date: Not shown in title block; ApprovedBy: Not shown in title block; CheckedBy: Not shown in title block; Author: Not shown in title block; CompanyName: Not shown in title block; Engineer: Not shown in title block; Organization: Not shown in title block; Address1: Not shown in title block; Address2: Not shown in title block; Address3: Not shown in title block; Address4: Not shown in title block; DocumentNumber: 7; Revision: Use project parameter SCH_Rev; SheetNumber: 7; SheetTotal: 8; PageSetup: Record=PageOptions|CenterHorizontal=True|CenterVertical=True|PrintScale=1.00|XCorrection=1.00|YCorrection=1.00|PrintKind=0|BorderSize=5000000|LeftOffset=0|BottomOffset=0|Orientation=2|PaperLength=1000|PaperWidth=1000|Scale=100|PaperSource=15|PrintQuality=600|MediaType=1|DitherType=10|PaperKind=Letter|PrintScaleMode=1
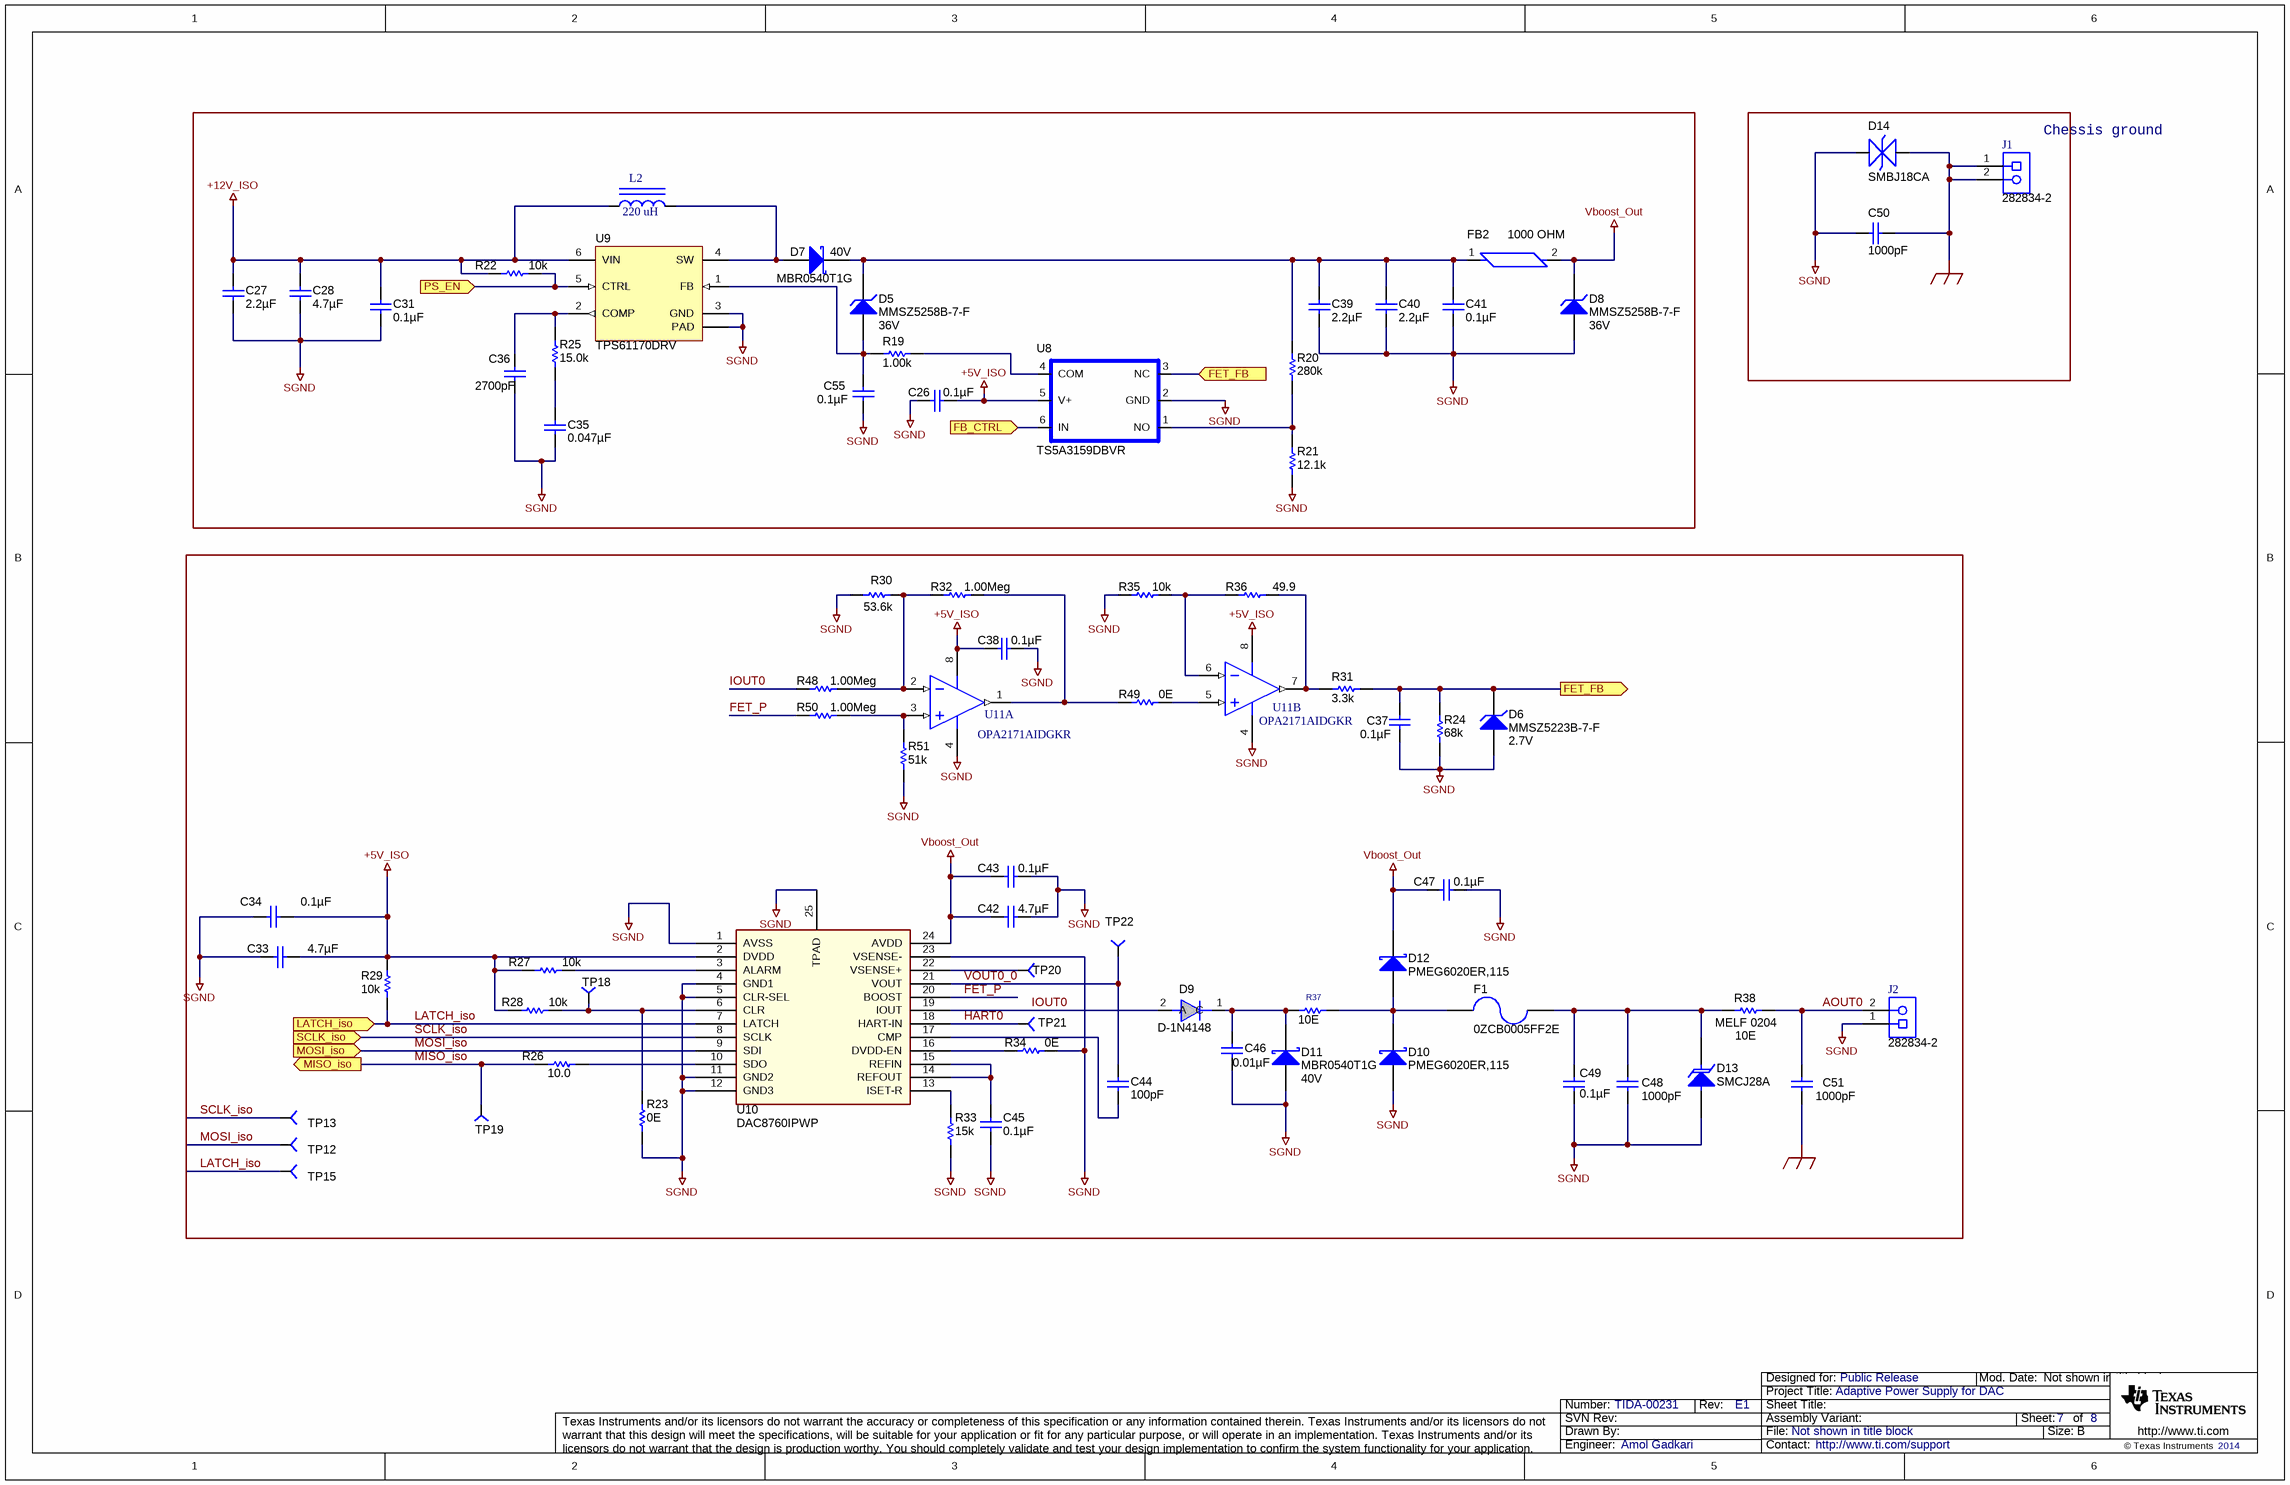
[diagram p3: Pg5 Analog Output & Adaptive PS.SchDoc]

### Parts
C26  ValueDisplayed: 0.1µF  [0603]  (hidden comment: 06035C104KAT2A)
C27  ValueDisplayed: 2.2µF  [1206]  (hidden comment: GRM31CR61H225KA88L)
C28  ValueDisplayed: 4.7µF  [0805]  (hidden comment: TMK212BJ475KG-T)
C31  ValueDisplayed: 0.1µF  [0603]  (hidden comment: 06035C104KAT2A)
C33  ValueDisplayed: 4.7µF  [0805_HV]  (hidden comment: C2012X5R1H475K125AB)
C34  ValueDisplayed: 0.1µF  [0603]  (hidden comment: 06035C104KAT2A)
C35  ValueDisplayed: 0.047µF  [0603]  (hidden comment: 06033C473JAT2A)
C36  ValueDisplayed: 2700pF  [0603_HV]  (hidden comment: GRM188R71H272KA01D)
C37  ValueDisplayed: 0.1µF  [0603]  (hidden comment: 06035C104KAT2A)
C38  ValueDisplayed: 0.1µF  [0603]  (hidden comment: 06035C104KAT2A)
C39  ValueDisplayed: 2.2µF  [1206]  (hidden comment: GRM31CR71H225KA88L)
C40  ValueDisplayed: 2.2µF  [1206]  (hidden comment: GRM31CR71H225KA88L)
C41  ValueDisplayed: 0.1µF  [0603]  (hidden comment: 06035C104KAT2A)
C42  ValueDisplayed: 4.7µF  [0805_HV]  (hidden comment: C2012X5R1H475K125AB)
C43  ValueDisplayed: 0.1µF  [0603]  (hidden comment: 06035C104KAT2A)
C44  ValueDisplayed: 100pF  [0603_HV]  (hidden comment: 06035A101JAT2A)
C45  ValueDisplayed: 0.1µF  [0603]  (hidden comment: 06035C104KAT2A)
C46  ValueDisplayed: 0.01µF  [0603]  (hidden comment: C0603C103K1RACTU)
C47  ValueDisplayed: 0.1µF  [0603]  (hidden comment: 06035C104KAT2A)
C48  value 1000pF  [1206]  (hidden comment: 202R18W102KV4E)
C49  ValueDisplayed: 0.1µF  [0603]  (hidden comment: 06035C104KAT2A)
C50  value 1000pF  [1206]  (hidden comment: 202R18W102KV4E)
C51  value 1000pF  [1206]  (hidden comment: 202R18W102KV4E)
C55  ValueDisplayed: 0.1µF  [0603]  (hidden comment: 06035C104KAT2A)
D5  MMSZ5258B-7-F  value 36V  [SOD-123]
D6  MMSZ5223B-7-F  value 2.7V  [SOD-123]
D7  MBR0540T1G  value 40V  [SOD-123]
D8  MMSZ5258B-7-F  value 36V  [SOD-123]
D9  D-1N4148  [D_SOD123]
D10  PMEG6020ER,115  [SOD-123F]
D11  MBR0540T1G  value 40V  [SOD-123]
D12  PMEG6020ER,115  [SOD-123F]
D13  SMCJ28A  [SMC]
D14  SMBJ18CA  [DIO_SMB_BIAAAA]
F1  0ZCB0005FF2E  [1210]
FB2  1000 OHM  [0603]
J1  282834-2  [TEC_282834-2]
J2  282834-2  [TEC_282834-2]
L2  value 220 uH  [IND_500X500_280]  (hidden comment: VLCF5028T-221MR22-2)
R19  value 1.00k  [0603]  (hidden comment: CRCW06031K00FKEA)
R20  value 280k  [0603_HV]  (hidden comment: RT0603BRD07280KL)
R21  value 12.1k  [0603_HV]  (hidden comment: RT0603BRD0712K1L)
R22  value 10k  [0402]  (hidden comment: CRCW040210K0JNED)
R23  value 0E  [0402]  (hidden comment: CRCW04020000Z0ED)
R24  value 68k  [0603]  (hidden comment: CRCW060368K0JNEA)
R25  value 15.0k  [0603]  (hidden comment: CRCW060315K0FKEA)
R26  value 10.0  [0603]  (hidden comment: CRCW060310R0FKEA)
R27  value 10k  [0402]  (hidden comment: CRCW040210K0JNED)
R28  value 10k  [0402]  (hidden comment: CRCW040210K0JNED)
R29  value 10k  [0402]  (hidden comment: CRCW040210K0JNED)
R30  value 53.6k  [0603]  (hidden comment: RC0603FR-0753K6L)
R31  value 3.3k  [0603]  (hidden comment: CRCW06033K30JNEA)
R32  value 1.00Meg  [0603]  (hidden comment: CRCW06031M00FKEA)
R33  value 15k  [0603]  (hidden comment: RT0603BRB0715KL)
R34  value 0E  [0402]  (hidden comment: CRCW04020000Z0ED)
R35  value 10k  [0603]  (hidden comment: CRCW060310K0JNEA)
R36  value 49.9  [0603]  (hidden comment: RT0603BRD0749R9L)
R37  value 10E  [1206]  (hidden comment: CRCW120610R0JNEA)
R38  value 10E  PackageReference: MELF 0204  [MMA0204]  (hidden comment: MMA02040C1009FB300)
R48  value 1.00Meg  [0603]  (hidden comment: CRCW06031M00FKEA)
R49  value 0E  [0402]  (hidden comment: CRCW04020000Z0ED)
R50  value 1.00Meg  [0603]  (hidden comment: CRCW06031M00FKEA)
R51  value 51k  [0603]  (hidden comment: CRCW060351K0JNEA)
TP12  TP-038  [TP1_PD40_D0.5_S50]  (value not drawn)
TP13  TP-038  [TP1_PD40_D0.5_S50]  (value not drawn)
TP15  TP-038  [TP1_PD40_D0.5_S50]  (value not drawn)
TP18  TP-038  [TP1_PD40_D0.5_S50]  (value not drawn)
TP19  TP-038  [TP1_PD40_D0.5_S50]  (value not drawn)
TP20  TP-038  [TP1_PD40_D0.5_S50]  (value not drawn)
TP21  TP-038  [TP1_PD40_D0.5_S50]  (value not drawn)
TP22  TP-038  [TP1_PD40_D0.5_S50]  (value not drawn)
U8  TS5A3159DBVR  [SOT23-6P]
U9  TPS61170DRV  [DRV0006A]
U10  DAC8760IPWP  [PWP24-DIE84X166]
U11  OPA2171AIDGKR  [DGK0008A_N]  (parts A,B of 2)

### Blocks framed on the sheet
Chessis ground: C50 D14 J1

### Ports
FB_CTRL (in), FET_FB (in), FET_FB (out), LATCH_iso (in), MISO_iso (out), MOSI_iso (in), PS_EN (in), SCLK_iso (in)

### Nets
+5V_ISO: C26.1 C33.2 C34.2 C38.1 R27.2 R28.2 R29.2 U8.5(V+) U10.2(DVDD) U11.8(V+)
+12V_ISO: C27.1 C28.1 C31.1 L2.1 R22.2 U9.6(VIN)
GND_EARTH: C50.2 C51.2 D14.2 J1.1 J1.2
SGND: C26.2 C27.2 C28.2 C31.2 C33.1 C34.1 C35.2 C36.2 C37.2 C38.2 C39.2 C40.2 C41.2 C42.1 C43.2 C45.1 C46.2 C47.2 C48.2 C49.2 C50.1 C55.2 D6.2(A) D8.2(A) D10.2(A) D11.2(A) D13.2(A) D14.1 J2.1 R21.1 R23.2 R24.1 R30.1 R33.2 R34.2 R35.1 R51.2 U8.2(GND) U9.3(GND) U9.7(PAD) U10.1(AVSS) U10.4(GND1) U10.5(CLR-SEL) U10.11(GND2) U10.12(GND3) U10.23(VSENSE-) U10.25(TPAD) U11.4(V-)
Vboost_Out: C42.2 C43.1 C47.1 D8.1(K) D12.1(K) FB2.2 U10.24(AVDD)
AOUT0: C51.1 J2.2 R38.2
FB_CTRL: U8.6(IN) ; port FB_CTRL
FET_FB: C37.1 D6.1(K) R24.2 R31.2 U8.3(NC) ; port FET_FB
FET_P: R50.1 U10.20(BOOST)
HART0: TP21.1 U10.18(HART-IN)
IOUT0: D9.2(A) R48.1 U10.19(IOUT)
LATCH_iso: R29.1 TP15.1 U10.7(LATCH) ; port LATCH_iso
MISO_iso: R26.1 TP19.1 ; port MISO_iso
MOSI_iso: TP12.1 U10.9(SDI) ; port MOSI_iso
PS_EN: R22.1 U9.5(CTRL) ; port PS_EN
SCLK_iso: TP13.1 U10.8(SCLK) ; port SCLK_iso
VOUT0_0: C44.1 TP22.1 U10.21(VOUT)
NetC35_1: C35.1 R25.1
NetC36_1: C36.1 R25.2 U9.2(COMP)
NetC39_1: C39.1 C40.1 C41.1 D5.1(K) D7.1(K) FB2.1 R20.2
NetC44_2: C44.2 U10.17(CMP)
NetC45_2: C45.2 U10.14(REFOUT) U10.15(REFIN)
NetC46_1: C46.1 D9.1(C) D11.1(K) R37.2
NetC48_1: C48.1 C49.1 D13.1(K) F1.1 R38.1
NetC55_1: C55.1 D5.2(A) R19.1 U9.1(FB)
NetD7_2: D7.2(A) L2.2 U9.4(SW)
NetD10_1: D10.1(K) D12.2(A) F1.2 R37.1
NetR19_2: R19.2 U8.4(COM)
NetR20_1: R20.1 R21.2 U8.1(NO)
NetR23_1: R23.1 R28.1 TP18.1 U10.6(CLR)
NetR26_2: R26.2 U10.10(SDO)
NetR27_1: R27.1 U10.3(ALARM)
NetR30_2: R30.2 R32.1 R48.2 U11.2(IN_A-)
NetR31_1: R31.1 R36.2 U11.7(OUT_B)
NetR32_2: R32.2 R49.1 U11.1(OUT_A)
NetR33_1: R33.1 U10.13(ISET-R)
NetR34_1: R34.1 U10.16(DVDD-EN)
NetR35_2: R35.2 R36.1 U11.6(IN_B-)
NetR49_2: R49.2 U11.5(IN_B+)
NetR50_2: R50.2 R51.1 U11.3(IN_A+)
NetTP20_1: TP20.1 U10.22(VSENSE+)

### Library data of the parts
C26 C31 C34 C37 C38 C41 C43 C45 C47 C49 C55 = 06035C104KAT2A: CAP, CERM, 0.1uF, 50V, +/-10%, X7R, 0603; Manufacturer: AVX; Polarized: N; CompType: Capacitor; U/M: EA; Cap_F: 0.0000001; Tolerance_%: 10; Value1: Unknown; VDC_V: 50; TaMin_C: -55; TaMax_C: 125
C27 = GRM31CR61H225KA88L: CAP, CERM, 2.2uF, 50V, +/-10%, X5R, 1206; Manufacturer: MuRata; Polarized: N; CompType: Capacitor; U/M: EA; Cap_F: 0.0000022; Tolerance_%: 10; Value1: Unknown; VDC_V: 50; TaMin_C: -55; TaMax_C: 85
C28 = TMK212BJ475KG-T: CAP, CERM, 4.7uF, 25V, +/-10%, X5R, 0805; Manufacturer: Taiyo Yuden; Polarized: N; CompType: Capacitor; U/M: EA; Cap_F: 0.0000047; Tolerance_%: 10; Value1: Unknown; VDC_V: 25; TaMin_C: -55; TaMax_C: 85
C33 C42 = C2012X5R1H475K125AB: as C30 on sheet Pg4 ISO Power Supply, I2C & SPI Isolators
C35 = 06033C473JAT2A: CAP, CERM, 0.047uF, 25V, +/-5%, X7R, 0603; Manufacturer: AVX; Polarized: N; CompType: Capacitor; U/M: EA; Cap_F: 0.000000047; Tolerance_%: 5; ESR_Ohm: 0.052; Value1: 0.052 ohm; VDC_V: 25; TaMin_C: -55; TaMax_C: 125
C36 = GRM188R71H272KA01D: CAP, CERM, 2700pF, 50V, +/-10%, X7R, 0603; Manufacturer: MuRata; Polarized: N; CompType: Capacitor; U/M: EA; Cap_F: 0.0000000027; Tolerance_%: 10; Value1: Unknown; VDC_V: 50; TaMin_C: -55; TaMax_C: 125; Cap_Case: 0603
C39 C40 = GRM31CR71H225KA88L: CAP, CERM, 2.2uF, 50V, +/-10%, X7R, 1206; Manufacturer: MuRata; Polarized: N; CompType: Capacitor; U/M: EA; Cap_F: 0.0000022; Tolerance_%: 10; Value1: Unknown; VDC_V: 50; TaMin_C: -55; TaMax_C: 125
C44 = 06035A101JAT2A: CAP, CERM, 100pF, 50V, +/-5%, C0G/NP0, 0603; Manufacturer: AVX; Polarized: N; CompType: Capacitor; U/M: EA; Cap_F: 0.0000000001; Tolerance_%: 5; ESR_Ohm: 0.119; Value1: 0.119 ohm; VDC_V: 50; TaMin_C: -55; TaMax_C: 125; Cap_Case: 0603
C46 = C0603C103K1RACTU: CAP, CERM, 0.01uF, 100V, +/-10%, X7R, 0603; Manufacturer: Kemet; Polarized: N; CompType: Capacitor; U/M: EA; Cap_F: 0.00000001; Tolerance_%: 10; Value1: Unknown; VDC_V: 100; TaMin_C: -55; TaMax_C: 125
C48 C50 C51 = 202R18W102KV4E: as C17 on sheet Pg4 ISO Power Supply, I2C & SPI Isolators
D5 D8 = MMSZ5258B-7-F: Diode, Zener, 36V, 500mW, SOD-123; Manufacturer: Diodes Inc.; SymbolCreator: a0412235; U/M: EA; Power_W: 0.5; Vz_V: 36; Value1: 0.5W; RJA_CperW: 350
D6 = MMSZ5223B-7-F: Diode, Zener, 2.7V, 500mW, SOD-123; Manufacturer: Diodes Inc.; SymbolCreator: a0412235; U/M: EA; Power_W: 0.5; Vz_V: 2.7; Value1: 0.5W; RJA_CperW: 350
D7 D11 = MBR0540T1G: Diode, Schottky, 40V, 0.5A, SOD-123; Manufacturer: ON Semiconductor; U/M: EA; Vf_V: 0.51; Value2: 0.51V; Io_A: 0.5; Vr_V: 40; TJmax_C: 150; RJC_CperW: 118
D9 = D-1N4148: Diode, Signal, 300-mA, 75-V, 350-mW; PartNumber: 1N4148W-7-F; Manufacturer: Diodes; Area: 13300; Value: 1N4148W-7-F
D10 D12 = PMEG6010CEH,115: DIODE SCHOTTKY 60V 2A SOD123W; Manufacturer: NXP Semiconductor; U/M: EA; Vf_V: 0.57; Value1: 1A; Value2: 0.57V; Io_A: 1; Vr_V: 60; TJmax_C: 150
D13 = SMCJ28A: Diode, TVS, Uni, 28V, 1500W, SMC; Manufacturer: Fairchild Semiconductor; U/M: EA; Power_W: 1500; Vr_V: 28
D14 = SMBJ18CA: TVS 18 VOLT 600 WATT BI-DIR SMB; Manufacturer: Littelfuse Inc
F1 = 37215000001: PTC RESTTBLE 0.05A 60V CHIP 1210; Manufacturer: Bel Fuse Inc; CompType: Fuse; U/M: EA; OpeningTime_100%_min: 4; OpeningTime_200%_max: 2; VDC_V: 60; Irating_A: 5; MeltingTyp: 94; Vdrop: 0.08; Soldering_Wave_MaxTemp_C: 260
FB2 = MMZ1608B102C: as FB1 on sheet Pg4 ISO Power Supply, I2C & SPI Isolators
J1 J2 = 282834-2: Terminal Block, 2x1, 2.54mm, TH; Manufacturer: TE Connectivity; SymbolCreator: a0412235; U/M: EA
L2 = VLCF5028T-221MR22-2: INDUCTOR POWER 220UH .22A SMD; Manufacturer: TDK Corporation; Area: 28000
R19 = CRCW06031K00FKEA: RES, 1.00k ohm, 1%, 0.1W, 0603; Manufacturer: Vishay-Dale; CompType: Resistor; Res_ohm: 1000; Value_Code: 1k00; Tolerance_%: 1; Power_W: 0.1; VDC_V: 75; TempCo: 100 ppm/C; EIA_Code: E96; U/M: EA
R20 = RT0603BRD07280KL: RES, 280k ohm, 0.1%, 0.1W, 0603; Manufacturer: Yageo America; CompType: Resistor; Res_ohm: 280000; Tolerance_%: 0.1; VDC_V: 75; TempCo: 25 ppm/C; EIA_Code: E192; U/M: EA
R21 = RT0603BRD0712K1L: RES, 12.1k ohm, 0.1%, 0.1W, 0603; Manufacturer: Yageo America; CompType: Resistor; Res_ohm: 12100; Value_Code: 12k1; Tolerance_%: 0.1; VDC_V: 75; TempCo: 25 ppm/C; EIA_Code: E192; U/M: EA
R22 R27-R29 = CRCW040210K0JNED: as R7 on sheet Pg4 ISO Power Supply, I2C & SPI Isolators
R23 R34 R49 = CRCW04020000Z0ED: RES, 0 ohm, 5%, 0.063W, 0402; Manufacturer: Vishay-Dale; CompType: Resistor; Res_ohm: 0; Value_Code: 0000; Tolerance_%: 5; Power_W: 0.063; VDC_V: 50; TempCo: 200 ppm/C; EIA_Code: E24; U/M: EA
R24 = CRCW060368K0JNEA: as R41 on sheet Pg4 ISO Power Supply, I2C & SPI Isolators
R25 = CRCW060315K0FKEA: RES, 15.0k ohm, 1%, 0.1W, 0603; Manufacturer: Vishay-Dale; CompType: Resistor; Res_ohm: 15000; Value_Code: 15k0; Tolerance_%: 1; Power_W: 0.1; VDC_V: 75; TempCo: 100 ppm/C; EIA_Code: E96; U/M: EA
R26 = CRCW060310R0FKEA: RES, 10.0 ohm, 1%, 0.1W, 0603; Manufacturer: Vishay-Dale; CompType: Resistor; Res_ohm: 10; Value_Code: 10R0; Tolerance_%: 1; Power_W: 0.1; VDC_V: 75; TempCo: 100 ppm/C; EIA_Code: E96; U/M: EA
R30 = RC0603FR-0753K6L: RES, 53.6k ohm, 1%, 0.1W, 0603; Manufacturer: Yageo America; CompType: Resistor; Res_ohm: 53600; Value_Code: 53k6; Tolerance_%: 1; Power_W: 0.1; VDC_V: 150; TempCo: 200 ppm/C; EIA_Code: E96; U/M: EA
R31 = CRCW06033K30JNEA: RES, 3.3k ohm, 5%, 0.1W, 0603; Manufacturer: Vishay-Dale; CompType: Resistor; Res_ohm: 3300; Value_Code: 3k30; Tolerance_%: 5; Power_W: 0.1; VDC_V: 75; TempCo: 200 ppm/C; EIA_Code: E24; U/M: EA
R32 R48 R50 = CRCW06031M00FKEA: RES, 1.00Meg ohm, 1%, 0.1W, 0603; Manufacturer: Vishay-Dale; CompType: Resistor; Res_ohm: 1000000; Value_Code: 1M00; Tolerance_%: 1; Power_W: 0.1; VDC_V: 75; TempCo: 100 ppm/C; EIA_Code: E96; U/M: EA
R33 = RT0603BRB0715KL: RES, 15k ohm, 1/10W 0.1% 0603; Manufacturer: Vishay-Dale; CompType: Resistor; Res_ohm: 15000; Tolerance_%: 0.1; Power_W: 1/10
R35 = CRCW060310K0JNEA: as R5 on sheet Pg3 Interboard conn, HS & EEPROM
R36 = RT0603BRD0749R9L: RES, 49.9 ohm, 0.1%, 0.1W, 0603; Manufacturer: Yageo America; CompType: Resistor; Value_Code: 49R9; Tolerance_%: 0.1; VDC_V: 75; TempCo: 25 ppm/C; EIA_Code: E192; U/M: EA
R37 = CRCW120610R0JNEA: RES, 10 ohm, 5%, 0.25W, 1206; Manufacturer: Vishay-Dale; CompType: Resistor; Res_ohm: 10; Value_Code: 10R0; Tolerance_%: 5; Power_W: 0.25; VDC_V: 200; TempCo: 200 ppm/C; EIA_Code: E24; U/M: EA
R38 = MMA02040C1000FB300: RES 10 OHM .4W 1% 0204 MELF; Manufacturer: Vishay Beyschlag; CompType: Resistor; Power_W: 0.5
R51 = CRCW060351K0JNEA: RES, 51k ohm, 5%, 0.1W, 0603; Manufacturer: Vishay-Dale; CompType: Resistor; Res_ohm: 51000; Value_Code: 51k0; Tolerance_%: 5; Power_W: 0.1; VDC_V: 75; TempCo: 200 ppm/C; EIA_Code: E24; U/M: EA
TP12 TP13 TP15 TP18-TP22 = TP-038: Test Point 40mil pad 20mil drill; Manufacturer: STD; Value: STD
U8 = TS5A3159DBVR: IC, 1 Ohm SPDT Analog Switch; PartNumber: TS5A3159ADBVR; Manufacturer: TI; Alternate Manufacturer: None; Area: 24336; Value: TS5A3159ADBVR
U9 = TPS61170DRV: 1.2A High Voltage Boost Converter in 2x2mm QFN Package, DRV0006A; Alternate Manufacturer: None; Manufacturer: Texas Instruments; SymbolCreator: a0411947; CompType: IC; U/M: EA
U10 = DAC8760IPWP: 1-Channel, 16-Bit, Programmable Current/Voltage Output DAC for 4-20mA Current Loop Applications; Manufacturer: Texas Instruments; CompType: IC; SymbolCreator: x0120606
U11 = OPA2171AIDGKR: Low Power, RRO, General Purpose Operational Amplifier in MicroPackage, 2.7 to 36 V, -40 to 125 degC, 8-pin SOP (DGK0008A), Green (RoHS & no Sb/Br); Manufacturer: Texas Instruments; Alternate Manufacturer: None; Alternate PartNumber: Equivalent; CMRR(Min)(dB): 104; GBW(Typ)(MHz): 3; IIB(Max)(pA): 15; Iq per channel(Max)(mA): 0.595; Number of Channels: 2; Offset Drift(Typ)(uV/C): 0.3; Packing: LARGE T&R; Rating: Catalog; Slew Rate(Typ)(V/us): 1.5; Sub Family: High Supply Voltage Amplifier (>=30V), Low Supply Voltage Amplifier (<=2.7V), Precision Amplifier; Total Supply Voltage(Max)(+5V is 5, +/-5V is 10): 36; Total Supply Voltage(Min)(+5V is 5, +/-5V is 10): 2.7; Vio (25C)(Max)(mV): 1.8

## Sheet Pg6 Hardware.SchDoc
size Letter
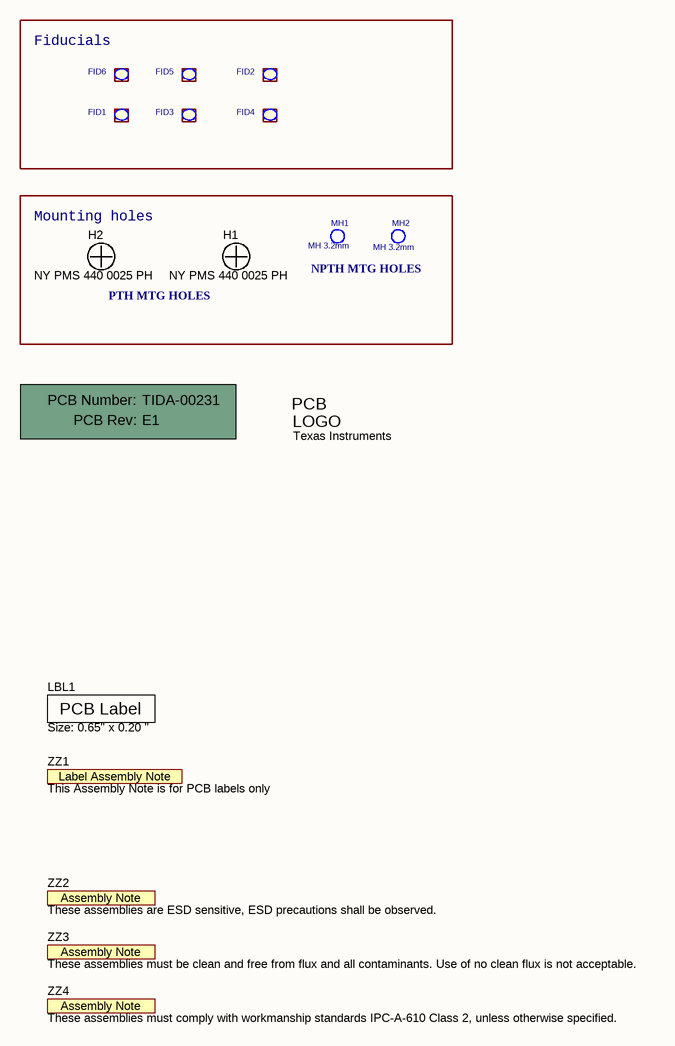
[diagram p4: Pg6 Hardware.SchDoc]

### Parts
!PCB  Printed Circuit Board  (value not drawn)  (mechanical)
FID1  Fiducial40_80  [FID_TOP_40_80BA]  (value not drawn)
FID2  Fiducial40_80  [FID_TOP_40_80BA]  (value not drawn)
FID3  Fiducial40_80  [FID_TOP_40_80BA]  (value not drawn)
FID4  Fiducial40_80  [FID_TOP_40_80BA]  (value not drawn)
FID5  Fiducial40_80  [FID_TOP_40_80BA]  (value not drawn)
FID6  Fiducial40_80  [FID_TOP_40_80BA]  (value not drawn)
H1  NY PMS 440 0025 PH  [NY PMS 440 0025 PH]
H2  NY PMS 440 0025 PH  [NY PMS 440 0025 PH]
LBL1  Size: 0.65" x 0.20 "  [Label_650x200]
Logo1  Texas Instruments  [TI_Stacked_SolderMask_Small]  (no BOM)
MH1  MH 3.2mm  [MH3.2_H5_W6_KO8_STARHEAD]
MH2  MH 3.2mm  [MH3.2_H5_W6_KO8_STARHEAD]
ZZ1  This Assembly Note is for PCB labels only  [AssemblyNoteLabel]  (no BOM)
ZZ2  These assemblies are ESD sensitive, ESD precautions shall be observed.  [AssemblyNote]  (no BOM)
ZZ3  These assemblies must be clean and free from flux and all contaminants. Use of no clean flux is not acceptable.  [AssemblyNote]  (no BOM)
ZZ4  These assemblies must comply with workmanship standards IPC-A-610 Class 2, unless otherwise specified.  [AssemblyNote]  (no BOM)

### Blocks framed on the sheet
Fiducials: FID1-FID6
Mounting holes: H1 H2 MH1 MH2

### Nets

Not connected (* = marked no-connect by the designer): FID1 1; FID2 1; FID3 1; FID4 1; FID5 1; FID6 1; MH1 1; MH2 1

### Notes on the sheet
- (near H2) PTH MTG HOLES
- NPTH MTG HOLES

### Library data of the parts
!PCB = PCB: Manufacturer: Any; PartNumber: TIDA-00231; SymbolCreator: a0412235
FID1-FID6 = Fiducial40_0
H1 H2 = NY PMS 440 0025 PH: Machine Screw, Round, #4-40 x 1/4, Nylon, Philips panhead; Manufacturer: B&F Fastener Supply; CompType: Hardware; SymbolCreator: codlsc; U/M: EA
LBL1 = THT-14-423-10: Thermal Transfer Printable Labels, 0.650" W x 0.200" H - 10,000 per roll; Manufacturer: Brady; SymbolCreator: a0412235; CompType: Label
Logo1 = TI_Logo: Texas Instrument Corporate Signature; SymbolCreator: codlsc
MH1 MH2 = MH 3_0.5MM: Mountin hole, NPTH Drill 3.2mm
ZZ1 = AssemblyNoteLabel: SymbolCreator: a0412235
ZZ2-ZZ4 = AssemblyNote: SymbolCreator: codlsc

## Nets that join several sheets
+3.3V_NON_ISO: Pg3 Interboard conn, HS & EEPROM (C4.2 R42.1 R43.1 U2.8), Pg4 ISO Power Supply, I2C & SPI Isolators (11 pins)
+5V_ISO: Pg4 ISO Power Supply, I2C & SPI Isolators (12 pins), Pg5 Analog Output & Adaptive PS (10 pins)
+12V_ISO: Pg4 ISO Power Supply, I2C & SPI Isolators (C22.1 D2.1 R52.2 TP16.1), Pg5 Analog Output & Adaptive PS (6 pins)
+24VDC_LIMIT: Pg3 Interboard conn, HS & EEPROM (6 pins), Pg4 ISO Power Supply, I2C & SPI Isolators (L1.1)
GND: Pg3 Interboard conn, HS & EEPROM (23 pins), Pg4 ISO Power Supply, I2C & SPI Isolators (21 pins)
SGND: Pg4 ISO Power Supply, I2C & SPI Isolators (25 pins), Pg5 Analog Output & Adaptive PS (48 pins)
/ALARM: Pg3 Interboard conn, HS & EEPROM (J3.6), Pg4 ISO Power Supply, I2C & SPI Isolators (R7.2 U5.2)
/CS0: Pg3 Interboard conn, HS & EEPROM (J3.1), Pg4 ISO Power Supply, I2C & SPI Isolators (U6.3)
FB_CTRL: Pg4 ISO Power Supply, I2C & SPI Isolators (R11.2 R16.1 TP9.1), Pg5 Analog Output & Adaptive PS (U8.6)
LATCH_iso: Pg4 ISO Power Supply, I2C & SPI Isolators (U6.14), Pg5 Analog Output & Adaptive PS (R29.1 TP15.1 U10.7)
MISO: Pg3 Interboard conn, HS & EEPROM (J3.5), Pg4 ISO Power Supply, I2C & SPI Isolators (U6.6)
MISO_iso: Pg4 ISO Power Supply, I2C & SPI Isolators (U6.11), Pg5 Analog Output & Adaptive PS (R26.1 TP19.1)
MOSI: Pg3 Interboard conn, HS & EEPROM (J3.7), Pg4 ISO Power Supply, I2C & SPI Isolators (U6.5)
MOSI_iso: Pg4 ISO Power Supply, I2C & SPI Isolators (R13.2), Pg5 Analog Output & Adaptive PS (TP12.1 U10.9)
PS_EN: Pg4 ISO Power Supply, I2C & SPI Isolators (R10.2 R15.1 TP8.1), Pg5 Analog Output & Adaptive PS (R22.1 U9.5)
RCLK: Pg3 Interboard conn, HS & EEPROM (J3.26), Pg4 ISO Power Supply, I2C & SPI Isolators (R8.1 U5.3)
SCLK: Pg3 Interboard conn, HS & EEPROM (J3.3), Pg4 ISO Power Supply, I2C & SPI Isolators (U6.4)
SCLK_iso: Pg4 ISO Power Supply, I2C & SPI Isolators (R12.2), Pg5 Analog Output & Adaptive PS (TP13.1 U10.8)

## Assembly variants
001: not fitted C6 C27 C36 C37 C48 D14 R7 R8 R15 R16 R22 R35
